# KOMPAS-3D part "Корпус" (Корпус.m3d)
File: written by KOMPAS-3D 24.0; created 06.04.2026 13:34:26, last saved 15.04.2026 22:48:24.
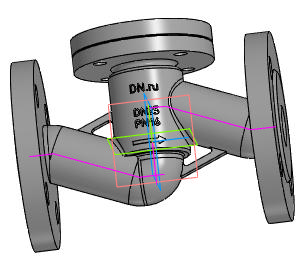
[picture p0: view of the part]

Document properties: Автор: R2D2; Полное имя файла: E:\Работа\Зайцев\VSO3131M-F-S Клапан запорный DN.ru Ду15-100 Ру16\DN25\исходные материалы\Корпус.m3d

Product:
- Body: Труба / Нестандартная труба / L = 79.1 мм  | qty 1
    Материал: Нестандартная труба (density 7856 kg/m3)
    Масса: 4.606135
    Раздел спецификации: Детали
    Примечание: 0,6 кг
    additional columns: Pipeline; 0.035; 0; 0; 0.002; 0.07905; true; 0.04
- Body: Труба / Нестандартная труба / L = 96.8 мм  | qty 1
    Материал: Нестандартная труба (density 7856 kg/m3)
    Масса: 4.606135
    Раздел спецификации: Детали
    Примечание: 0,73 кг
    additional columns: Pipeline; 0.035; 0; 0; 0.002; 0.09675; true; 0.04
- Body: Тело 4  | qty 1
    Материал: Нестандартная труба (density 7856 kg/m3)
    Масса: 4.606135
- Body: Тело 5  | qty 1
    Материал: Нестандартная труба (density 7856 kg/m3)
    Масса: 4.606135
- Body: Тело 8  | qty 1
    Материал: Нестандартная труба (density 7856 kg/m3)
    Масса: 4.606135
- Body: Тело 9  | qty 1
    Материал: Нестандартная труба (density 7856 kg/m3)
    Масса: 4.606135
- Part/product: Корпус
    Масса: 6.9

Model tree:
1. Труба
2. Труба:1  (labels: {F703FF30-5BE6-4673-A7F1-8EDA1BE1E2D1}; SHAPEOBJECT3D_ATTR_BUTT; SHAPEOBJECT3D_ATTR_VALID; SHAPEOBJECT3D_ATTR_BUTT_AREA)
     PIPE_R = 7
3. Труба:2  (labels: {F703FF30-5BE6-4673-A7F1-8EDA1BE1E2D1}; SHAPEOBJECT3D_ATTR_BUTT; SHAPEOBJECT3D_ATTR_VALID; SHAPEOBJECT3D_ATTR_BUTT_AREA)
     PIPE_R = 7
4. Колонна
5. Элемент выдавливания:1
     Смещение 1 = -1; Смещение 2 = -5
6. Скругление:17  (with: Ребро.Элемент выдавливания:1)
     Радиус = 1
7. Скругление:18  (with: Ребро.Элемент выдавливания:1)
8. Скругление:24  (with: Ребро.Элемент выдавливания:1)
     Радиус = 1.5
9. Элемент выдавливания:2
     Расстояние 1 = 6
10. Скругление:19  (with: Ребро.Элемент выдавливания:2)
     Радиус = 2
11. Эскиз:4  (with: Грань.Элемент выдавливания:1)
12. Элемент выдавливания:3
     Расстояние 1 = 4
13. Скругление:21  (with: Ребро.Элемент выдавливания:3)
14. ОТЛИВКА
15. Скругление:6  (with: Грань.Элемент выдавливания:1)
     Радиус = 2
16. Элемент выдавливания:6  (with: Грань.Элемент выдавливания:1)
     Смещение 1 = 4
17. ЛЕЙБЛ
18. Элемент выдавливания:7  (with: Грань.Элемент выдавливания:1)
     Расстояние 1 = 23.4986; Смещение 1 = 1
19. Фланец верх  (with: Ребро.Элемент выдавливания:3)
20. Элемент вращения:2
     Угол 1 = 360
21. Эскиз:12  (with: Грань.Элемент вращения:2)
22. Элемент выдавливания:9  (with: Грань.Элемент вращения:2)
     Расстояние 2 = 20
23. Массив по концентрической сетке:1  (with: Элемент выдавливания:9, Эскиз:12, Грань.Элемент вращения:2)  (4 pattern instances)
     Шаг 2 = 360
24. Фланец
25. Элемент вращения:1
     Угол 1 = 360
26. Эскиз:10  (with: Грань.Элемент вращения:1)
27. Элемент выдавливания:8
28. Массив по концентрической сетке:2  (with: Элемент выдавливания:8, Эскиз:10, Грань.Элемент вращения:1)  (4 pattern instances)
     Шаг 2 = 360
29. Зеркальный массив:1
30. Экземпляр ( 1 )
31. Экземпляр ( 2 )  (with: Элемент вращения:1, Массив по концентрической сетке:2, Экземпляр ( 1 ), Элемент выдавливания:8)
32. Экземпляр ( 3 )  (with: Элемент выдавливания:8)
33. Экземпляр ( 4 )  (with: Элемент выдавливания:8)
34. Скругление:25  (with: Ребро.Элемент вращения:2)
     Радиус = 2

Expressions: DS/2+3; D1/2; DN/2; DS-v977*4; LL/2; D1-v1234*2; D/2-11
Referenced files in C:\Program Files\ASCON\KOMPAS-3D v24\Libs\Pipeline\: StylesTemplate.a3d, TemplateHPH, InsulationStylesTemplate.a3d, Insulation
Referenced files in C:\Program Files\ASCON\KOMPAS-3D v24\Templates\: Констр. чертеж А3 гориз. перв. лист.cdt
Referenced files in E:\Работа\Зайцев\VSO3131M-F-S Клапан запорный DN.ru Ду15-100 Ру40\DN20\исходные материалы\: 
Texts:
  Отводы ГОСТ 17375-2001
  Констр. чертеж А3 гориз. перв. лист.cdt
  GOST 26.020 Pr3
  var3D
  GOST 2.304 type A
  смещение колонны вниз
  LL-10
  DN+10
  Труба / Нестандартная труба / L = %s мм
